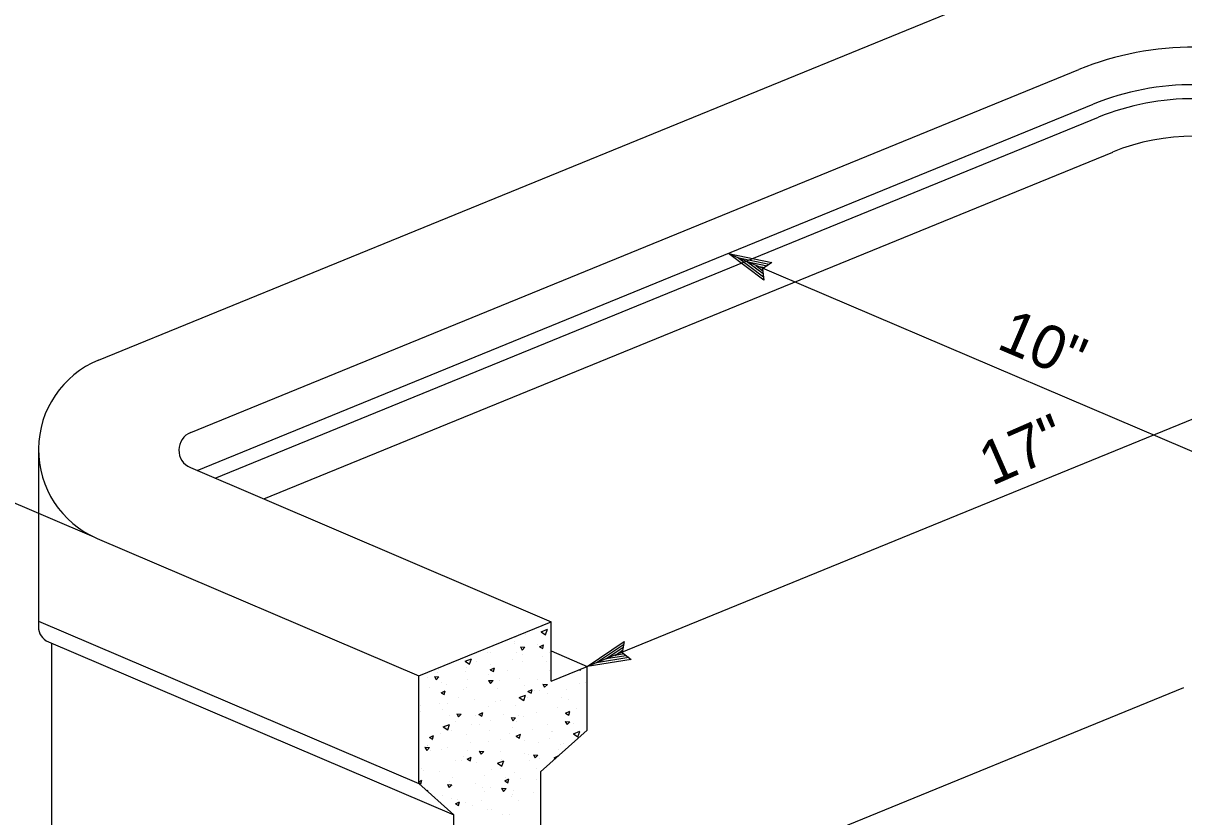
# Model space of a CAD drawing. Extents: x -121875 to -117742, y -103854 to -101122.
# Drawn here: x -120967 to -120806.9, y -101430.4 to -101320.8 of the extents above; entities that cross this region are included whole.
import ezdxf

# ---------------------------------------------------------------- set-up
doc = ezdxf.new("R2010")
doc.units = 0
for name, color, linetype in [('G-MARK', 7, 'Continuous'), ('G-TEXT', 7, 'Continuous'), ('Misc CnstDet(22)', 7, 'Continuous')]:
    doc.layers.add(name, color=color, linetype=linetype)

msp = doc.modelspace()

# ---------------------------------------------------------------- linework, layer by layer
at = {"layer": 'G-MARK'}
for p, q in [((-120746.67, -101351.36), (-120889.21, -101409.62)), ((-120869.73, -101352.6), (-120787.86, -101387.59)), ((-120957.26, -101391.76), (-120990.02, -101377.76))]:
    msp.add_line(p, q, dxfattribs=at)
at = {"layer": 'G-TEXT'}
for p, q in [((-120864.82, -101356.29), (-120869.73, -101352.6)), ((-120869.73, -101352.6), (-120869.73, -101352.6)), ((-120869.73, -101352.6), (-120863.72, -101353.86)), ((-120864.87, -101355.88), (-120868.48, -101353.17)), ((-120868.46, -101353.17), (-120864.08, -101354.09)), ((-120864.93, -101355.45), (-120867.22, -101353.74)), ((-120867.22, -101353.74), (-120864.38, -101354.33)), ((-120864.95, -101355.07), (-120865.96, -101354.31)), ((-120865.96, -101354.31), (-120864.75, -101354.56)), ((-120863.72, -101353.86), (-120865, -101354.74)), ((-120863.72, -101353.86), (-120863.72, -101353.86)), ((-120865, -101354.74), (-120864.82, -101356.29)), ((-120864.82, -101356.29), (-120864.82, -101356.29)), ((-120889.21, -101409.62), (-120884.12, -101406.17)), ((-120887.92, -101409.1), (-120884.2, -101406.59)), ((-120886.64, -101408.6), (-120884.24, -101406.98)), ((-120885.35, -101408.1), (-120884.33, -101407.4)), ((-120884.12, -101406.17), (-120884.37, -101407.7)), ((-120884.12, -101406.17), (-120884.12, -101406.17)), ((-120883.14, -101408.66), (-120889.21, -101409.62)), ((-120883.47, -101408.4), (-120887.92, -101409.11)), ((-120883.82, -101408.16), (-120886.64, -101408.6)), ((-120884.11, -101407.9), (-120885.35, -101408.1)), ((-120884.37, -101407.7), (-120883.14, -101408.66)), ((-120883.14, -101408.66), (-120883.14, -101408.66)), ((-120889.21, -101409.62), (-120889.21, -101409.62))]:
    msp.add_line(p, q, dxfattribs=at)
at = {"layer": 'Misc CnstDet(22)'}
for p, q in [((-120956.64, -101367.35), (-120826.66, -101314.22)), ((-120943.92, -101377.33), (-120821.35, -101327.22)), ((-120943.04, -101382.57), (-120819.39, -101332.02)), ((-120940.54, -101383.64), (-120818.65, -101333.81)), ((-120933.84, -101386.5), (-120816.69, -101338.61)), ((-120964.93, -101379.58), (-120964.93, -101404.14)), ((-120943.96, -101382.17), (-120894.18, -101403.45)), ((-120956.84, -101391.95), (-120912.45, -101410.92)), ((-120964.93, -101403.37), (-120912.45, -101425.8)), ((-120912.45, -101410.92), (-120894.18, -101403.45)), ((-120894.18, -101411.65), (-120894.18, -101403.45)), ((-120899.15, -101405.65), (-120899.15, -101405.65)), ((-120897.73, -101405.25), (-120897.73, -101405.25)), ((-120895.58, -101404.84), (-120894.7, -101404.5)), ((-120895.58, -101404.84), (-120894.95, -101405.26)), ((-120894.95, -101405.26), (-120894.7, -101404.5)), ((-120963.56, -101406.22), (-120907.62, -101430.13)), ((-120963.09, -101462.49), (-120963.09, -101406.42)), ((-120899.28, -101406.16), (-120899.28, -101406.16)), ((-120899.21, -101406.44), (-120899.21, -101406.44)), ((-120898.42, -101406.93), (-120898.17, -101407.36)), ((-120898.42, -101406.93), (-120897.8, -101406.97)), ((-120898.17, -101407.36), (-120897.8, -101406.97)), ((-120896.12, -101406.6), (-120896.12, -101406.6)), ((-120895.79, -101406.92), (-120895.22, -101406.65)), ((-120895.79, -101406.92), (-120895.35, -101407.17)), ((-120895.35, -101407.17), (-120895.22, -101406.66)), ((-120894.18, -101407.49), (-120889.21, -101409.62)), ((-120907.91, -101409.12), (-120907.91, -101409.12)), ((-120906.07, -101408.91), (-120905.19, -101408.57)), ((-120906.07, -101408.91), (-120905.44, -101409.32)), ((-120905.44, -101409.33), (-120905.19, -101408.57)), ((-120904.45, -101408.93), (-120904.45, -101408.93)), ((-120902.93, -101407.65), (-120902.93, -101407.65)), ((-120902.53, -101407.7), (-120902.53, -101407.7)), ((-120899.49, -101408.65), (-120899.49, -101408.65)), ((-120899, -101407.73), (-120899, -101407.73)), ((-120898.17, -101408.94), (-120898.17, -101408.94)), ((-120898.16, -101407.92), (-120898.16, -101407.92)), ((-120895.33, -101408.21), (-120895.33, -101408.21)), ((-120894.87, -101409), (-120894.87, -101409)), ((-120894.45, -101407.74), (-120894.45, -101407.74)), ((-120909.8, -101410.42), (-120909.8, -101410.42)), ((-120909.75, -101410.11), (-120909.75, -101410.11)), ((-120906.03, -101410.34), (-120906.03, -101410.34)), ((-120905.9, -101409.75), (-120905.9, -101409.75)), ((-120902.87, -101410.71), (-120902.87, -101410.71)), ((-120902.58, -101409.3), (-120902.58, -101409.3)), ((-120902.58, -101410.09), (-120902.02, -101409.82)), ((-120902.58, -101410.09), (-120902.15, -101410.34)), ((-120902.15, -101410.34), (-120902.02, -101409.83)), ((-120900.26, -101410.2), (-120900.26, -101410.2)), ((-120894.43, -101410.25), (-120894.43, -101410.25)), ((-120894.21, -101409.97), (-120894.21, -101409.97)), ((-120894.18, -101411.65), (-120889.21, -101409.62)), ((-120890.83, -101410.3), (-120890.83, -101410.3)), ((-120890.32, -101410.07), (-120890.16, -101410.17)), ((-120890.16, -101410.17), (-120890.11, -101409.98)), ((-120889.21, -101418.43), (-120889.21, -101409.62)), ((-120912.45, -101425.8), (-120912.45, -101410.92)), ((-120911.29, -101411.17), (-120911.29, -101411.17)), ((-120910.3, -101411.02), (-120910.04, -101411.45)), ((-120910.3, -101411.02), (-120909.67, -101411.07)), ((-120910.04, -101411.46), (-120909.67, -101411.07)), ((-120909.28, -101411.8), (-120909.28, -101411.8)), ((-120908.68, -101412.18), (-120908.68, -101412.18)), ((-120905.71, -101411.4), (-120905.71, -101411.4)), ((-120902.82, -101411.55), (-120902.56, -101411.98)), ((-120902.82, -101411.55), (-120902.19, -101411.59)), ((-120902.56, -101411.98), (-120902.19, -101411.59)), ((-120901.28, -101411.63), (-120901.28, -101411.63)), ((-120898.62, -101411.35), (-120898.62, -101411.35)), ((-120897.8, -101412.3), (-120897.8, -101412.3)), ((-120896.13, -101411.47), (-120896.13, -101411.47)), ((-120895.33, -101412.07), (-120895.08, -101412.5)), ((-120895.33, -101412.07), (-120894.71, -101412.11)), ((-120895.08, -101412.5), (-120894.71, -101412.12)), ((-120890.26, -101412.02), (-120890.26, -101412.02)), ((-120889.39, -101411.84), (-120889.39, -101411.84)), ((-120911.02, -101412.58), (-120911.02, -101412.58)), ((-120909.38, -101413.26), (-120908.81, -101412.99)), ((-120909.38, -101413.26), (-120908.95, -101413.51)), ((-120908.95, -101413.51), (-120908.81, -101413)), ((-120906.98, -101413.88), (-120906.98, -101413.88)), ((-120906.24, -101412.76), (-120906.24, -101412.76)), ((-120905.85, -101412.47), (-120905.85, -101412.47)), ((-120901.52, -101412.67), (-120901.52, -101412.67)), ((-120898.59, -101413.91), (-120897.72, -101413.58)), ((-120898.59, -101413.91), (-120897.97, -101414.33)), ((-120897.97, -101414.33), (-120897.72, -101413.58)), ((-120897.4, -101413.94), (-120897.4, -101413.94)), ((-120897.39, -101413.09), (-120896.82, -101412.82)), ((-120897.39, -101413.09), (-120896.95, -101413.34)), ((-120896.95, -101413.34), (-120896.82, -101412.83)), ((-120896.52, -101412.93), (-120896.52, -101412.93)), ((-120895.8, -101412.94), (-120895.8, -101412.94)), ((-120895.64, -101448.82), (-120806.88, -101412.53)), ((-120894.67, -101413.4), (-120894.67, -101413.4)), ((-120892.76, -101413.89), (-120892.76, -101413.89)), ((-120892.09, -101412.77), (-120892.09, -101412.77)), ((-120912.28, -101415.05), (-120912.28, -101415.05)), ((-120909.62, -101414.81), (-120909.62, -101414.81)), ((-120908.45, -101414.7), (-120908.45, -101414.7)), ((-120904.73, -101414.23), (-120904.73, -101414.23)), ((-120902.79, -101415.14), (-120902.79, -101415.14)), ((-120901.89, -101414.52), (-120901.89, -101414.52)), ((-120901.18, -101414.36), (-120901.18, -101414.36)), ((-120899.17, -101414.99), (-120899.17, -101414.99)), ((-120893.36, -101415.24), (-120893.36, -101415.24)), ((-120891.76, -101414.23), (-120891.76, -101414.23)), ((-120890.72, -101415.45), (-120890.72, -101415.45)), ((-120912.17, -101415.9), (-120912.17, -101415.9)), ((-120909.14, -101415.61), (-120909.14, -101415.61)), ((-120908.24, -101416.35), (-120908.24, -101416.35)), ((-120907.21, -101416.17), (-120906.95, -101416.6)), ((-120907.21, -101416.17), (-120906.58, -101416.21)), ((-120906.95, -101416.6), (-120906.58, -101416.21)), ((-120904.56, -101416.41), (-120904.56, -101416.41)), ((-120904.18, -101416.26), (-120903.62, -101415.99)), ((-120904.18, -101416.26), (-120903.75, -101416.51)), ((-120903.75, -101416.51), (-120903.62, -101416)), ((-120903.69, -101415.99), (-120903.69, -101415.99)), ((-120902.55, -101417.04), (-120902.55, -101417.04)), ((-120900.77, -101416.28), (-120900.77, -101416.28)), ((-120899.72, -101416.69), (-120899.47, -101417.12)), ((-120899.72, -101416.69), (-120899.1, -101416.73)), ((-120899.47, -101417.12), (-120899.1, -101416.74)), ((-120898.66, -101416.42), (-120898.66, -101416.42)), ((-120897.94, -101416.57), (-120897.94, -101416.57)), ((-120896.14, -101415.95), (-120896.14, -101415.95)), ((-120892.19, -101416.09), (-120891.62, -101415.82)), ((-120892.19, -101416.09), (-120891.76, -101416.34)), ((-120891.76, -101416.34), (-120891.62, -101415.83)), ((-120912.41, -101418.78), (-120912.41, -101418.78)), ((-120909.08, -101417.98), (-120908.21, -101417.64)), ((-120909.08, -101417.98), (-120908.46, -101418.4)), ((-120908.46, -101418.4), (-120908.2, -101417.64)), ((-120907.93, -101418.46), (-120907.93, -101418.46)), ((-120907.41, -101417.2), (-120907.41, -101417.2)), ((-120905.19, -101417.66), (-120905.19, -101417.66)), ((-120904.05, -101417.61), (-120904.05, -101417.61)), ((-120902.65, -101418.5), (-120902.65, -101418.5)), ((-120899.51, -101418), (-120899.51, -101418)), ((-120898.93, -101417.29), (-120898.93, -101417.29)), ((-120896.82, -101418.33), (-120896.82, -101418.33)), ((-120895.64, -101424.19), (-120889.21, -101418.43)), ((-120894.62, -101417.71), (-120894.62, -101417.71)), ((-120894.18, -101418.59), (-120894.18, -101418.59)), ((-120893.99, -101418.62), (-120893.99, -101418.62)), ((-120892.24, -101417.21), (-120891.99, -101417.64)), ((-120892.24, -101417.21), (-120891.62, -101417.26)), ((-120891.98, -101417.64), (-120891.62, -101417.26)), ((-120891.11, -101418.92), (-120890.24, -101418.58)), ((-120891.07, -101417.54), (-120891.07, -101417.54)), ((-120890.49, -101419.34), (-120890.24, -101418.59)), ((-120910.98, -101419.43), (-120910.41, -101419.16)), ((-120910.98, -101419.43), (-120910.55, -101419.68)), ((-120910.55, -101419.68), (-120910.41, -101419.17)), ((-120910.52, -101419.89), (-120910.52, -101419.89)), ((-120909.5, -101418.82), (-120909.5, -101418.82)), ((-120905.93, -101419.09), (-120905.93, -101419.09)), ((-120905.32, -101420.08), (-120905.32, -101420.08)), ((-120902.89, -101420.05), (-120902.89, -101420.05)), ((-120901.23, -101419.71), (-120901.23, -101419.71)), ((-120899.93, -101418.89), (-120899.93, -101418.89)), ((-120898.99, -101419.26), (-120898.42, -101418.99)), ((-120898.99, -101419.26), (-120898.55, -101419.51)), ((-120898.55, -101419.51), (-120898.42, -101419)), ((-120897.9, -101419.79), (-120897.9, -101419.79)), ((-120895.89, -101420.18), (-120895.89, -101420.18)), ((-120894.45, -101419.59), (-120894.45, -101419.59)), ((-120892.87, -101420.38), (-120892.87, -101420.38)), ((-120892.44, -101420.23), (-120892.44, -101420.23)), ((-120891.11, -101418.92), (-120890.49, -101419.34)), ((-120890.44, -101418.97), (-120890.44, -101418.97)), ((-120911.6, -101420.79), (-120911.34, -101421.22)), ((-120911.6, -101420.79), (-120910.97, -101420.83)), ((-120911.34, -101421.22), (-120910.97, -101420.83)), ((-120911.31, -101420.51), (-120911.31, -101420.51)), ((-120911.29, -101420.54), (-120911.29, -101420.54)), ((-120910.77, -101421.29), (-120910.77, -101421.29)), ((-120909.3, -101421.15), (-120909.3, -101421.15)), ((-120908.46, -101420.84), (-120908.46, -101420.84)), ((-120905.76, -101421.19), (-120905.76, -101421.19)), ((-120904.12, -101421.31), (-120903.86, -101421.74)), ((-120904.12, -101421.31), (-120903.49, -101421.35)), ((-120903.86, -101421.74), (-120903.49, -101421.36)), ((-120901.19, -101421.36), (-120901.19, -101421.36)), ((-120897.83, -101421.65), (-120897.83, -101421.65)), ((-120897.28, -101421.76), (-120897.28, -101421.76)), ((-120896.63, -101421.83), (-120896.38, -101422.26)), ((-120896.63, -101421.83), (-120896.01, -101421.88)), ((-120896.38, -101422.26), (-120896.01, -101421.88)), ((-120893.79, -101422.26), (-120893.22, -101421.99)), ((-120893.23, -101422.04), (-120893.22, -101422)), ((-120893.14, -101421.09), (-120893.14, -101421.09)), ((-120907.34, -101422.59), (-120907.34, -101422.59)), ((-120906.58, -101422.55), (-120906.58, -101422.55)), ((-120906.27, -101422.1), (-120906.27, -101422.1)), ((-120905.78, -101422.43), (-120905.22, -101422.16)), ((-120905.78, -101422.43), (-120905.35, -101422.68)), ((-120905.35, -101422.68), (-120905.22, -101422.17)), ((-120904.51, -101422.89), (-120904.51, -101422.89)), ((-120901.6, -101422.99), (-120900.73, -101422.65)), ((-120901.6, -101422.99), (-120900.98, -101423.41)), ((-120901, -101422.49), (-120901, -101422.49)), ((-120900.98, -101423.41), (-120900.73, -101422.65)), ((-120897.15, -101422.65), (-120897.15, -101422.65)), ((-120895.82, -101422.28), (-120895.82, -101422.28)), ((-120893.79, -101422.26), (-120893.6, -101422.37)), ((-120912.03, -101423.76), (-120912.03, -101423.76)), ((-120911.75, -101423.97), (-120911.75, -101423.97)), ((-120909.64, -101424.15), (-120909.64, -101424.15)), ((-120907.85, -101425.02), (-120907.85, -101425.02)), ((-120903.39, -101424.64), (-120903.39, -101424.64)), ((-120902.46, -101423.83), (-120902.46, -101423.83)), ((-120901.2, -101423.7), (-120901.2, -101423.7)), ((-120900.59, -101425.43), (-120900.02, -101425.16)), ((-120900.55, -101424.94), (-120900.55, -101424.94)), ((-120900.16, -101425.68), (-120900.02, -101425.17)), ((-120899.2, -101424.33), (-120899.2, -101424.33)), ((-120898.42, -101425.13), (-120898.42, -101425.13)), ((-120896.24, -101423.78), (-120896.24, -101423.78)), ((-120895.64, -101424.19), (-120895.64, -101457.8)), ((-120912.45, -101425.54), (-120912.02, -101425.33)), ((-120912.45, -101425.67), (-120912.15, -101425.85)), ((-120907.62, -101430.13), (-120912.45, -101425.8)), ((-120912.15, -101425.85), (-120912.02, -101425.33)), ((-120911.37, -101426.77), (-120911.22, -101426.72)), ((-120911.27, -101426.86), (-120911.22, -101426.72)), ((-120908.51, -101425.93), (-120908.25, -101426.36)), ((-120908.51, -101425.93), (-120907.88, -101425.97)), ((-120908.25, -101426.36), (-120907.88, -101425.98)), ((-120908.17, -101425.55), (-120908.17, -101425.55)), ((-120907.8, -101426.02), (-120907.8, -101426.02)), ((-120904.58, -101425.75), (-120904.58, -101425.75)), ((-120903.72, -101426.3), (-120903.72, -101426.3)), ((-120902.57, -101426.38), (-120902.57, -101426.38)), ((-120901.03, -101426.45), (-120900.77, -101426.88)), ((-120901.03, -101426.45), (-120900.4, -101426.5)), ((-120900.77, -101426.88), (-120900.4, -101426.5)), ((-120900.59, -101425.43), (-120900.16, -101425.68)), ((-120899.43, -101426.69), (-120899.43, -101426.69)), ((-120896.16, -101425.29), (-120896.16, -101425.29)), ((-120909.11, -101427.5), (-120909.11, -101427.5)), ((-120907.95, -101427.8), (-120907.95, -101427.8)), ((-120907.39, -101428.6), (-120906.82, -101428.33)), ((-120907.14, -101428.05), (-120907.14, -101428.05)), ((-120906.95, -101428.85), (-120906.82, -101428.33)), ((-120903.85, -101428.07), (-120903.85, -101428.07)), ((-120903.41, -101426.85), (-120903.41, -101426.85)), ((-120899.68, -101427.6), (-120899.68, -101427.6)), ((-120899.54, -101427.34), (-120899.54, -101427.34)), ((-120898.66, -101428.14), (-120898.66, -101428.14)), ((-120896.6, -101426.99), (-120896.6, -101426.99)), ((-120907.39, -101428.6), (-120906.95, -101428.85)), ((-120905.95, -101428.44), (-120905.95, -101428.44)), ((-120904.98, -101428.77), (-120904.98, -101428.77)), ((-120902.91, -101429.39), (-120902.91, -101429.39)), ((-120902.38, -101429.35), (-120902.38, -101429.35)), ((-120907.62, -101462.7), (-120907.62, -101430.13)), ((-120900.94, -101430.07), (-120900.94, -101430.07)), ((-120899.89, -101430.12), (-120899.89, -101430.12))]:
    msp.add_line(p, q, dxfattribs=at)
for centre, radius, start, end in [((-120805.66, -101365.61), 41.47, 66.8572, 112.2327), ((-120805.66, -101365.61), 36.29, 66.8572, 112.2327), ((-120805.66, -101365.61), 34.35, 66.8572, 112.2327), ((-120805.66, -101365.61), 29.17, 66.8572, 112.2327), ((-120951.6, -101379.69), 13.33, 112.2327, 246.8572), ((-120942.93, -101379.76), 2.63, 112.2327, 246.8572), ((-120962.67, -101404.14), 2.27, 180, 246.8572)]:
    msp.add_arc(centre, radius, start, end, dxfattribs=at)

# ---------------------------------------------------------------- texts
for s, rotation, p in [('10"', 336.8572, (-120832.88, -101365.64)), ('17"', 23.6156, (-120833.38, -101384.75))]:
    msp.add_text(s, height=6, rotation=rotation, dxfattribs=at).set_placement(p)

doc.saveas('drawing.dxf')
